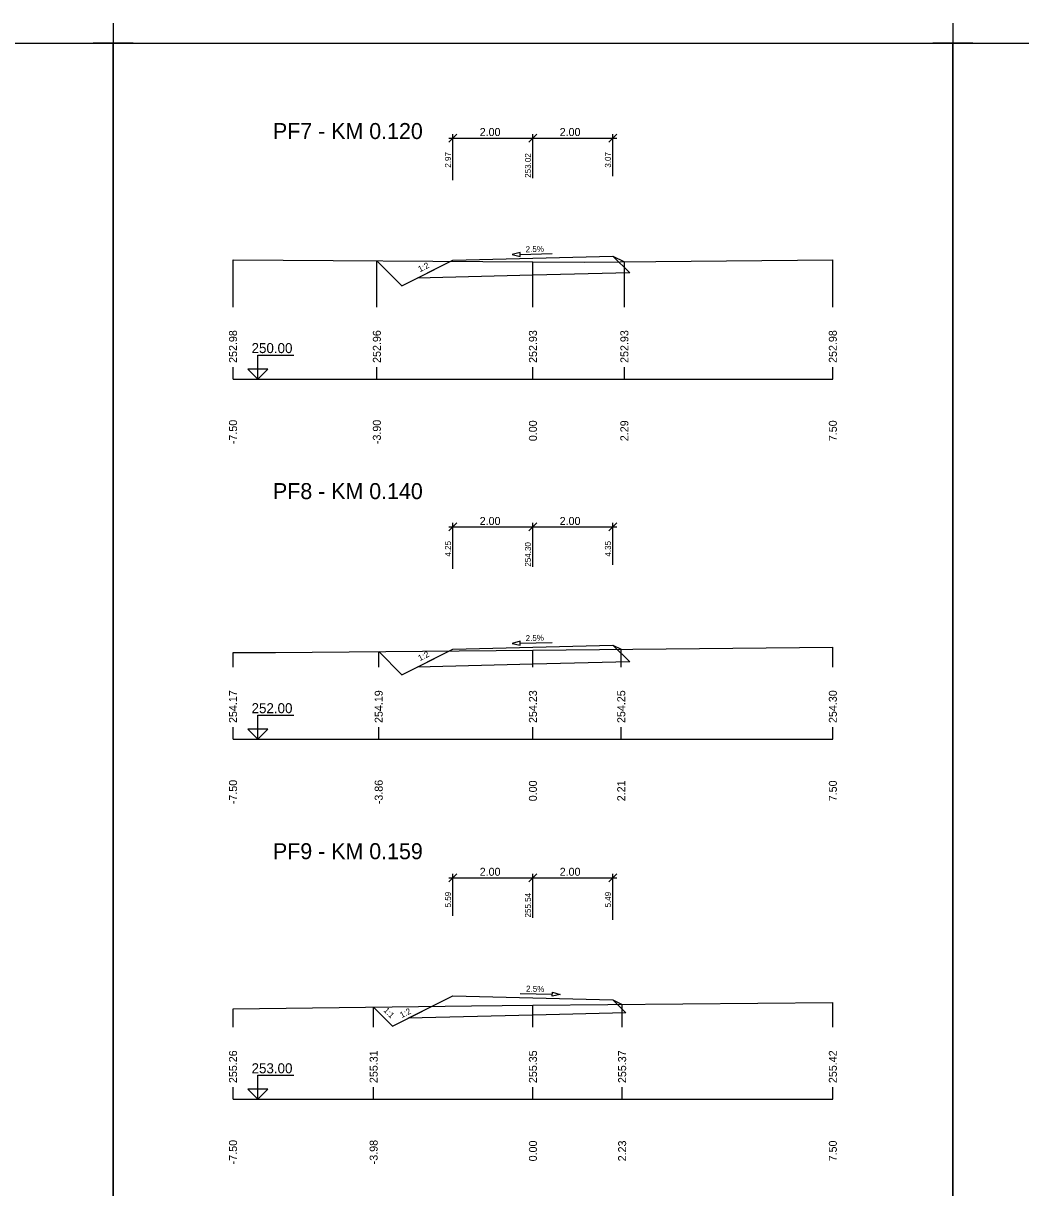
# Model space of a CAD drawing. Extents: x -1895 to 2525, y -19 to 585.
# Drawn here: x -1492.4 to -1243, y 293.9 to 584.9 of the extents above; entities that cross this region are included whole.
import ezdxf

# ---------------------------------------------------------------- set-up
doc = ezdxf.new("R2010")
doc.units = 0
for name, color, linetype in [('KOTA', 7, 'Continuous'), ('KOTA_DELKY', 7, 'Continuous'), ('KOTA_DELKY_CONT', 7, 'Continuous'), ('NS_TELESO_VOZOVKY', 7, 'Continuous'), ('NS_V_PF', 7, 'Continuous'), ('REZY_PF_PUVODNI', 7, 'Continuous'), ('SESTAVY_REZU_PF', 7, 'Continuous'), ('SKLON', 7, 'Continuous'), ('SVK', 7, 'Continuous')]:
    doc.layers.add(name, color=color, linetype=linetype)

msp = doc.modelspace()

# ---------------------------------------------------------------- linework, layer by layer
for p, q in [((-1469.95, 584.93), (-1469.95, 574.93)), ((-1469.95, 584.93), (-1469.95, 574.93)), ((-1259.95, 584.93), (-1259.95, 574.93)), ((-1259.95, 584.93), (-1259.95, 574.93)), ((-1464.95, 579.93), (-1474.95, 579.93)), ((-1464.95, 579.93), (-1474.95, 579.93)), ((-1254.95, 579.93), (-1264.95, 579.93)), ((-1254.95, 579.93), (-1264.95, 579.93))]:
    msp.add_line(p, q)
for points in [[(-1679.95, 579.93), (-1469.95, 579.93), (-1469.95, 282.93), (-1679.95, 282.93)], [(-1469.95, 579.93), (-1259.95, 579.93), (-1259.95, 282.93), (-1469.95, 282.93)], [(-1259.95, 579.93), (-1049.95, 579.93), (-1049.95, 282.93), (-1259.95, 282.93)]]:
    msp.add_lwpolyline(points, close=True)
at = {"layer": 'KOTA'}
for points in [[(-1433.73, 498.5), (-1436.23, 498.5), (-1433.73, 496), (-1433.73, 502), (-1424.73, 502)], [(-1433.73, 496), (-1431.23, 498.5), (-1433.73, 498.5)], [(-1433.73, 408.5), (-1436.23, 408.5), (-1433.73, 406), (-1433.73, 412), (-1424.73, 412)], [(-1433.73, 406), (-1431.23, 408.5), (-1433.73, 408.5)], [(-1433.73, 318.5), (-1436.23, 318.5), (-1433.73, 316), (-1433.73, 322), (-1424.73, 322)], [(-1433.73, 316), (-1431.23, 318.5), (-1433.73, 318.5)]]:
    msp.add_lwpolyline(points, dxfattribs=at)
at = {"layer": 'KOTA_DELKY'}
for points in [[(-1385.95, 555.25), (-1383.95, 557.25)], [(-1385.95, 556.25), (-1363.95, 556.25)], [(-1384.95, 545.75), (-1384.95, 557.25)], [(-1365.95, 555.25), (-1363.95, 557.25)], [(-1365.95, 555.25), (-1363.95, 557.25)], [(-1365.95, 556.25), (-1343.95, 556.25)], [(-1364.95, 546.25), (-1364.95, 557.25)], [(-1364.95, 546.25), (-1364.95, 557.25)], [(-1345.95, 555.25), (-1343.95, 557.25)], [(-1344.95, 546.75), (-1344.95, 557.25)], [(-1385.95, 458.04), (-1383.95, 460.04)], [(-1384.95, 448.54), (-1384.95, 460.04)], [(-1365.95, 458.04), (-1363.95, 460.04)], [(-1365.95, 458.04), (-1363.95, 460.04)], [(-1364.95, 449.04), (-1364.95, 460.04)], [(-1364.95, 449.04), (-1364.95, 460.04)], [(-1345.95, 458.04), (-1343.95, 460.04)], [(-1344.95, 449.54), (-1344.95, 460.04)], [(-1385.95, 459.04), (-1363.95, 459.04)], [(-1365.95, 459.04), (-1343.95, 459.04)], [(-1385.95, 370.36), (-1383.95, 372.36)], [(-1385.95, 371.36), (-1363.95, 371.36)], [(-1384.95, 361.86), (-1384.95, 372.36)], [(-1365.95, 370.36), (-1363.95, 372.36)], [(-1365.95, 370.36), (-1363.95, 372.36)], [(-1365.95, 371.36), (-1343.95, 371.36)], [(-1364.95, 361.36), (-1364.95, 372.36)], [(-1364.95, 361.36), (-1364.95, 372.36)], [(-1345.95, 370.36), (-1343.95, 372.36)], [(-1344.95, 360.86), (-1344.95, 372.36)]]:
    msp.add_lwpolyline(points, dxfattribs=at)
at = {"layer": 'NS_TELESO_VOZOVKY'}
for points in [[(-1364.95, 526.25), (-1344.95, 526.75), (-1344.95, 526.75), (-1340.75, 522.55), (-1364.95, 521.95), (-1393.89, 521.22), (-1384.95, 525.75), (-1384.95, 525.75), (-1364.95, 526.25)], [(-1364.95, 429.04), (-1344.95, 429.54), (-1344.95, 429.54), (-1340.75, 425.35), (-1364.95, 424.74), (-1393.89, 424.02), (-1384.95, 428.54), (-1384.95, 428.54), (-1364.95, 429.04)], [(-1364.95, 341.36), (-1344.95, 340.86), (-1344.95, 340.86), (-1341.73, 337.64), (-1364.95, 337.06), (-1396.11, 336.28), (-1384.95, 341.86), (-1384.95, 341.86), (-1364.95, 341.36)]]:
    msp.add_lwpolyline(points, dxfattribs=at)
at = {"layer": 'NS_V_PF'}
for points in [[(-1403.98, 525.56), (-1397.76, 519.27), (-1384.95, 525.75), (-1384.95, 525.75), (-1364.95, 526.25), (-1344.95, 526.75), (-1344.95, 526.75), (-1342.08, 525.31)], [(-1403.52, 427.89), (-1397.76, 422.07), (-1384.95, 428.54), (-1384.95, 428.54), (-1364.95, 429.04), (-1344.95, 429.54), (-1344.95, 429.54), (-1342.86, 428.5)], [(-1404.78, 339.05), (-1400.09, 334.29), (-1384.95, 341.86), (-1384.95, 341.86), (-1364.95, 341.36), (-1344.95, 340.86), (-1344.95, 340.86), (-1342.64, 339.71)]]:
    msp.add_lwpolyline(points, dxfattribs=at)
at = {"layer": 'REZY_PF_PUVODNI'}
for points in [[(-1439.95, 525.8), (-1364.95, 525.3), (-1351.94, 525.21), (-1289.95, 525.84)], [(-1439.95, 427.7), (-1429.35, 427.63), (-1364.95, 428.28), (-1289.95, 429.03)], [(-1439.95, 338.59), (-1380.3, 339.38), (-1364.95, 339.51), (-1289.95, 340.17)]]:
    msp.add_lwpolyline(points, dxfattribs=at)
at = {"layer": 'SESTAVY_REZU_PF'}
for points in [[(-1439.95, 496), (-1289.95, 496)], [(-1439.95, 406), (-1289.95, 406)], [(-1439.95, 316), (-1289.95, 316)]]:
    msp.add_lwpolyline(points, dxfattribs=at)
at = {"layer": 'SKLON'}
for points in [[(-1368.16, 527.67), (-1370.15, 527.12), (-1368.14, 526.67), (-1368.16, 527.67)], [(-1368.15, 527.17), (-1360.15, 527.37)], [(-1368.16, 430.47), (-1370.15, 429.92), (-1368.14, 429.47), (-1368.16, 430.47)], [(-1368.15, 429.97), (-1360.15, 430.17)], [(-1368.1, 342.44), (-1360.1, 342.24)], [(-1360.09, 342.74), (-1358.1, 342.19), (-1360.11, 341.74), (-1360.09, 342.74)]]:
    msp.add_lwpolyline(points, dxfattribs=at)
at = {"layer": 'SVK'}
for points in [[(-1439.95, 514), (-1439.95, 525.8)], [(-1403.98, 514), (-1403.98, 525.56)], [(-1364.95, 514), (-1364.95, 525.3)], [(-1342.08, 514), (-1342.08, 525.31)], [(-1289.95, 514), (-1289.95, 525.84)], [(-1439.95, 496), (-1439.95, 499)], [(-1403.98, 496), (-1403.98, 499)], [(-1364.95, 496), (-1364.95, 499)], [(-1342.08, 496), (-1342.08, 499)], [(-1289.95, 496), (-1289.95, 499)], [(-1403.52, 424), (-1403.52, 427.89)], [(-1364.95, 424), (-1364.95, 428.28)], [(-1342.86, 424), (-1342.86, 428.5)], [(-1289.95, 424), (-1289.95, 429.03)], [(-1439.95, 424), (-1439.95, 427.7)], [(-1439.95, 406), (-1439.95, 409)], [(-1403.52, 406), (-1403.52, 409)], [(-1364.95, 406), (-1364.95, 409)], [(-1342.86, 406), (-1342.86, 409)], [(-1289.95, 406), (-1289.95, 409)], [(-1439.95, 334), (-1439.95, 338.59)], [(-1404.78, 334), (-1404.78, 339.05)], [(-1364.95, 334), (-1364.95, 339.51)], [(-1342.64, 334), (-1342.64, 339.71)], [(-1289.95, 334), (-1289.95, 340.17)], [(-1439.95, 316), (-1439.95, 319)], [(-1404.78, 316), (-1404.78, 319)], [(-1364.95, 316), (-1364.95, 319)], [(-1342.64, 316), (-1342.64, 319)], [(-1289.95, 316), (-1289.95, 319)]]:
    msp.add_lwpolyline(points, dxfattribs=at)

# ---------------------------------------------------------------- texts
at = {"layer": 'KOTA'}
for s, p in [('250.00', (-1435.31, 502.5)), ('252.00', (-1435.31, 412.5)), ('253.00', (-1435.31, 322.5))]:
    msp.add_text(s, height=2.5, dxfattribs=at).set_placement(p)
at = {"layer": 'KOTA_DELKY'}
for p in [(-1378.26, 556.75), (-1358.26, 556.75), (-1378.26, 459.54), (-1358.26, 459.54), (-1378.26, 371.86), (-1358.26, 371.86)]:
    msp.add_text('2.00', height=2, dxfattribs=at).set_placement(p)
at = {"layer": 'KOTA_DELKY_CONT'}
for s, p in [('2.97', (-1385.45, 548.84)), ('253.02', (-1365.45, 546.32)), ('3.07', (-1345.45, 548.84)), ('4.25', (-1385.45, 451.63)), ('254.30', (-1365.45, 449.12)), ('4.35', (-1345.45, 451.63)), ('5.59', (-1385.45, 363.95)), ('255.54', (-1365.45, 361.44)), ('5.49', (-1345.45, 363.95))]:
    msp.add_text(s, height=1.5, rotation=90, dxfattribs=at).set_placement(p)
at = {"layer": 'SESTAVY_REZU_PF'}
for s, p in [('PF7 - KM 0.120', (-1429.95, 556)), ('PF8 - KM 0.140', (-1429.95, 466)), ('PF9 - KM 0.159', (-1429.95, 376))]:
    msp.add_text(s, height=4, dxfattribs=at).set_placement(p)
at = {"layer": 'SKLON'}
for s, rotation, p in [('2.5%', 1.4321, (-1366.75, 527.7)), ('1:2', 26.8233, (-1393.21, 522.69)), ('2.5%', 1.4321, (-1366.75, 430.5)), ('1:2', 26.8233, (-1393.21, 425.49)), ('2.5%', 358.5679, (-1366.68, 342.9)), ('1:1', 314.5713, (-1402.43, 338.1)), ('1:2', 26.5484, (-1397.76, 336.28))]:
    msp.add_text(s, height=1.5, rotation=rotation, dxfattribs=at).set_placement(p)
at = {"layer": 'SVK'}
for s, p in [(' 252.98', (-1438.95, 499.3)), (' 252.96', (-1402.98, 499.3)), (' 252.93', (-1363.95, 499.3)), (' 252.93', (-1341.08, 499.3)), (' 252.98', (-1288.95, 499.3)), (' -7.50', (-1438.95, 479)), (' -3.90', (-1402.98, 479)), ('  0.00', (-1363.95, 479)), ('  2.29', (-1341.08, 479)), ('  7.50', (-1288.95, 479)), (' 254.17', (-1438.95, 409.3)), (' 254.19', (-1402.52, 409.3)), (' 254.23', (-1363.95, 409.3)), (' 254.25', (-1341.86, 409.3)), (' 254.30', (-1288.95, 409.3)), (' -7.50', (-1438.95, 389)), (' -3.86', (-1402.52, 389)), ('  0.00', (-1363.95, 389)), ('  2.21', (-1341.86, 389)), ('  7.50', (-1288.95, 389)), (' 255.26', (-1438.95, 319.3)), (' 255.31', (-1403.78, 319.3)), (' 255.35', (-1363.95, 319.3)), (' 255.37', (-1341.64, 319.3)), (' 255.42', (-1288.95, 319.3)), (' -7.50', (-1438.95, 299)), (' -3.98', (-1403.78, 299)), ('  0.00', (-1363.95, 299)), ('  7.50', (-1288.95, 299)), ('  2.23', (-1341.64, 299))]:
    msp.add_text(s, height=2, rotation=90, dxfattribs=at).set_placement(p)

doc.saveas('drawing.dxf')
